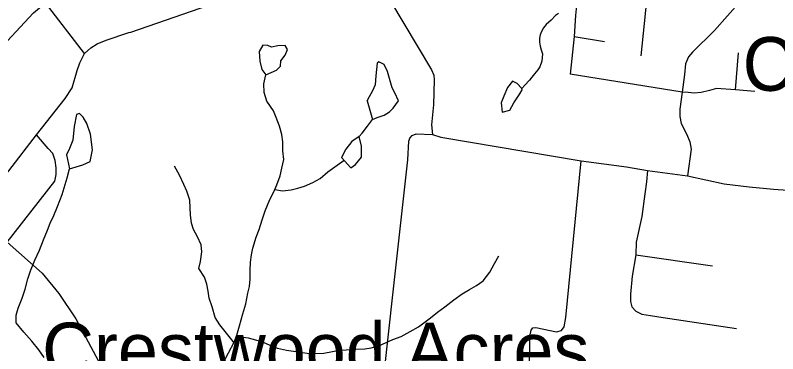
# Model space of a CAD drawing. Extents: x 0 to 34, y 0 to 22.
# Drawn here: x 2.395 to 3.515, y 16.285 to 16.783 of the extents above; entities that cross this region are included whole.
import ezdxf

# ---------------------------------------------------------------- set-up
doc = ezdxf.new("R2010")
doc.units = 0
for name, color, linetype in [('GM_X_County_Road', 7, 'Continuous'), ('GM_X_Interstate_Route', 7, 'Continuous'), ('GM_X_Minor_Lake', 7, 'Continuous'), ('GM_X_Minor_River', 7, 'Continuous'), ('GM_X_Township_Subdivision', 7, 'Continuous'), ('GM_X_Unincorporated_Text', 7, 'Continuous')]:
    doc.layers.add(name, color=color, linetype=linetype)

msp = doc.modelspace()

# ---------------------------------------------------------------- linework, layer by layer
at = {"layer": 'GM_X_County_Road'}
for points in [[(2.5645, 16.7579), (2.6921, 16.8018), (2.7129, 16.8072), (2.7415, 16.8122), (2.8434, 16.8208), (2.8888, 16.8307), (2.925, 16.8393)], [(2.925, 16.8393), (3.0063, 16.7023), (3.0099, 16.6947), (3.0101, 16.6874), (3.0094, 16.6508), (3.0062, 16.6215), (3.0077, 16.6072)], [(2.4966, 16.7263), (2.4393, 16.8007), (2.4357, 16.8056)], [(2.3395, 16.5036), (2.3546, 16.5175), (2.3853, 16.5537), (2.4262, 16.6065), (2.4679, 16.6603), (2.4783, 16.676), (2.4859, 16.7014), (2.4895, 16.7128), (2.4966, 16.7263), (2.5057, 16.7348), (2.5149, 16.7406), (2.5283, 16.7461), (2.5618, 16.757), (2.5645, 16.7579)], [(2.3831, 16.4487), (2.4531, 16.5388), (2.4547, 16.5483), (2.4548, 16.5581), (2.4534, 16.5688), (2.4501, 16.5791), (2.4433, 16.5867), (2.4262, 16.6065)], [(2.8559, 15.3242), (2.8828, 15.5776), (2.8823, 15.5871), (2.88, 15.6009), (2.8808, 15.6183), (2.8941, 15.7652), (2.913, 15.9963), (2.9286, 16.1743), (2.9306, 16.1979), (2.9499, 16.3756), (2.9714, 16.57), (2.9729, 16.5972), (2.9738, 16.6003), (2.9747, 16.6018), (2.978, 16.6059), (2.9836, 16.6083), (3.0077, 16.6072)], [(3.0077, 16.6072), (3.0199, 16.6034), (3.2263, 16.5685), (3.2928, 16.5595), (3.3237, 16.5541), (3.3826, 16.5464), (3.4363, 16.5348), (3.4732, 16.5304), (3.5089, 16.527), (3.5443, 16.5245), (3.6987, 16.5072), (3.6996, 16.5071)], [(3.2878, 15.9702), (3.2906, 16.01), (3.287, 16.0204), (3.2811, 16.0285), (3.1838, 16.1424), (3.1651, 16.1641), (3.1565, 16.1802), (3.1523, 16.1945), (3.1498, 16.2167), (3.1509, 16.3102), (3.153, 16.3194), (3.1554, 16.3229), (3.1594, 16.3234), (3.1901, 16.3171), (3.1974, 16.3189), (3.2011, 16.3245), (3.2039, 16.3381), (3.2263, 16.5685)], [(2.2074, 16.5345), (2.2273, 16.5312), (2.2755, 16.511), (2.3238, 16.4892), (2.3831, 16.4487), (2.4345, 16.4035), (2.4589, 16.3735), (2.484, 16.336), (2.5458, 16.2199), (2.6419, 16.0249), (2.6836, 15.948), (2.7291, 15.8843), (2.758, 15.8531), (2.7648, 15.8462)]]:
    msp.add_lwpolyline(points, dxfattribs=at)
at = {"layer": 'GM_X_Interstate_Route'}
msp.add_lwpolyline([(2.181, 16.4629), (2.2273, 16.5312), (2.2674, 16.589), (2.34, 16.6943), (2.3633, 16.7237), (2.4215, 16.7861), (2.4393, 16.8007), (2.4586, 16.8179), (2.4894, 16.8393), (2.7155, 16.9908), (2.8497, 17.0804), (2.9292, 17.1425), (3.0025, 17.2108), (3.0522, 17.2646), (3.1203, 17.3605), (3.2374, 17.5377), (3.2788, 17.5999), (3.3097, 17.642), (3.3406, 17.6772), (3.3886, 17.7251), (3.5019, 17.8134), (3.5855, 17.8769), (3.6539, 17.9292), (3.721, 17.9807)], dxfattribs=at)
at = {"layer": 'GM_X_Minor_Lake'}
for points in [[(2.7627, 16.6952), (2.7784, 16.7018), (2.7843, 16.7077), (2.7852, 16.7157), (2.7911, 16.7239), (2.7947, 16.7322), (2.7914, 16.7383), (2.7808, 16.7378), (2.7712, 16.7358), (2.7659, 16.7382), (2.7587, 16.7387), (2.7532, 16.7293), (2.754, 16.7152)], [(2.754, 16.7152), (2.7572, 16.7026), (2.7627, 16.6952)], [(2.9196, 16.6293), (2.9265, 16.6324), (2.9368, 16.6356), (2.9446, 16.6407), (2.95, 16.6459), (2.9578, 16.6568), (2.9524, 16.6683), (2.9484, 16.676), (2.9445, 16.6897), (2.9417, 16.7001), (2.937, 16.7104), (2.9291, 16.714), (2.9264, 16.7122), (2.9245, 16.6936), (2.9238, 16.6803), (2.9198, 16.6713), (2.9147, 16.6627), (2.9115, 16.6563)], [(2.9196, 16.6293), (2.9265, 16.6324), (2.9368, 16.6356), (2.9446, 16.6407), (2.95, 16.6459), (2.9578, 16.6568), (2.9524, 16.6683), (2.9484, 16.676), (2.9445, 16.6897), (2.9417, 16.7001), (2.937, 16.7104), (2.9291, 16.714), (2.9264, 16.7122), (2.9245, 16.6936), (2.9238, 16.6803), (2.9198, 16.6713), (2.9147, 16.6627), (2.9116, 16.6566)], [(3.139, 16.6747), (3.132, 16.6822), (3.1252, 16.6857), (3.1178, 16.6764)], [(3.1178, 16.6764), (3.1126, 16.6636), (3.1085, 16.6538), (3.1101, 16.6401), (3.1212, 16.6429), (3.1275, 16.6538), (3.1362, 16.6669), (3.1393, 16.6729), (3.139, 16.6747)], [(2.9116, 16.6566), (2.9196, 16.6293)], [(2.4743, 16.5569), (2.4939, 16.5626), (2.505, 16.5673), (2.5084, 16.5847), (2.5055, 16.6076), (2.4998, 16.6233), (2.4947, 16.6329), (2.4891, 16.6383), (2.4849, 16.6365), (2.4811, 16.6188), (2.4795, 16.5987), (2.4747, 16.5866), (2.4703, 16.5772)], [(2.8893, 16.5971), (2.8807, 16.5856), (2.8739, 16.5736), (2.888, 16.5584), (2.8946, 16.5632), (2.9036, 16.574), (2.9035, 16.59), (2.9001, 16.6045)], [(2.9001, 16.6045), (2.8893, 16.5971)], [(2.4703, 16.5772), (2.4743, 16.5569)]]:
    msp.add_lwpolyline(points, dxfattribs=at)
at = {"layer": 'GM_X_Minor_River'}
for points in [[(3.193, 16.7854), (3.1883, 16.7821), (3.182, 16.7754), (3.175, 16.7691), (3.1711, 16.7643), (3.1679, 16.7587), (3.1659, 16.7538), (3.165, 16.7488), (3.1652, 16.7431), (3.1662, 16.737), (3.1675, 16.7316), (3.1693, 16.7259), (3.1686, 16.7152), (3.1654, 16.7069), (3.1626, 16.7021), (3.1578, 16.6965), (3.1539, 16.6916), (3.1504, 16.6872), (3.1433, 16.6798), (3.139, 16.6747)], [(2.7023, 16.2748), (2.7083, 16.2861), (2.7163, 16.3019), (2.7203, 16.3121), (2.7244, 16.3257), (2.7291, 16.3434), (2.7336, 16.3581), (2.7366, 16.3737), (2.7388, 16.3835), (2.7398, 16.3945), (2.7397, 16.4071), (2.7404, 16.4196), (2.7418, 16.4302), (2.744, 16.44), (2.7485, 16.4563), (2.753, 16.4676), (2.7575, 16.4819), (2.762, 16.4951), (2.7689, 16.5117), (2.7749, 16.523), (2.7789, 16.5331), (2.7838, 16.5463), (2.7863, 16.5577), (2.7893, 16.5705), (2.7881, 16.5831), (2.7877, 16.5964), (2.7864, 16.6071), (2.7829, 16.6197), (2.7783, 16.6324), (2.7743, 16.642), (2.7644, 16.656), (2.7606, 16.669), (2.7601, 16.6815), (2.7627, 16.6952)], [(2.9001, 16.6045), (2.9043, 16.6092), (2.9121, 16.6193), (2.9196, 16.6293)], [(2.7763, 16.5265), (2.7874, 16.5242), (2.8, 16.5258), (2.8099, 16.5282), (2.8195, 16.531), (2.8322, 16.5368), (2.8426, 16.5426), (2.8538, 16.5522), (2.8778, 16.5695)], [(2.7159, 16.3011), (2.7151, 16.3027), (2.6952, 16.3271), (2.6883, 16.3379), (2.6841, 16.3536), (2.6798, 16.3667), (2.6782, 16.3766), (2.6762, 16.3873), (2.6726, 16.3973), (2.6646, 16.41), (2.6667, 16.4206), (2.669, 16.4346), (2.6681, 16.4449), (2.6627, 16.4565), (2.6568, 16.4673), (2.6537, 16.4769), (2.652, 16.4891), (2.6519, 16.4993), (2.6511, 16.5108), (2.6468, 16.5238), (2.6425, 16.5338), (2.636, 16.5473), (2.6287, 16.5604)], [(2.4372, 16.2794), (2.4295, 16.2903), (2.4191, 16.3031), (2.4073, 16.3163), (2.3962, 16.3302), (2.3961, 16.3413), (2.399, 16.3519), (2.4047, 16.3665), (2.4092, 16.3798), (2.4134, 16.3949), (2.4171, 16.4066), (2.4236, 16.4224), (2.4304, 16.437), (2.4361, 16.4525), (2.4421, 16.4664), (2.4462, 16.4766), (2.4514, 16.4883), (2.4566, 16.5014), (2.4635, 16.5191), (2.4681, 16.5335), (2.471, 16.5433), (2.4743, 16.5569)], [(2.7198, 16.3108), (2.7263, 16.3096), (2.7369, 16.3082), (2.7479, 16.3053), (2.7588, 16.3016), (2.7686, 16.2976), (2.7799, 16.2931), (2.7931, 16.2901), (2.8034, 16.2887), (2.8132, 16.287), (2.8238, 16.2856), (2.8348, 16.2849), (2.8481, 16.2854), (2.8607, 16.2881), (2.8706, 16.2901), (2.8809, 16.2903), (2.895, 16.2914), (2.9083, 16.2919), (2.9178, 16.2932), (2.9289, 16.2963), (2.9397, 16.3014), (2.9497, 16.3057), (2.962, 16.3103), (2.975, 16.3173), (2.987, 16.3242), (3.0048, 16.3378), (3.0149, 16.3459), (3.0257, 16.3537), (3.0393, 16.364), (3.0513, 16.3728), (3.0624, 16.3794), (3.0725, 16.3849), (3.0821, 16.3922), (3.0919, 16.4045), (3.0991, 16.4177), (3.1051, 16.4289)]]:
    msp.add_lwpolyline(points, dxfattribs=at)
at = {"layer": 'GM_X_Township_Subdivision'}
for points in [[(3.2267, 16.9013), (3.2264, 16.898), (3.2266, 16.87), (3.2207, 16.8119), (3.2179, 16.7821), (3.2161, 16.7511), (3.2099, 16.6961)], [(3.8766, 16.8608), (3.8386, 16.8639), (3.6602, 16.8815), (3.5812, 16.8884), (3.5665, 16.887), (3.553, 16.8832), (3.541, 16.877), (3.5216, 16.8628), (3.4605, 16.8035), (3.4221, 16.7604), (3.3897, 16.7285), (3.3838, 16.7214), (3.3793, 16.711), (3.3779, 16.6956), (3.3748, 16.6696), (3.3712, 16.6447), (3.371, 16.6339), (3.3731, 16.6233), (3.3815, 16.607), (3.3861, 16.5965), (3.388, 16.5857), (3.3826, 16.5464)], [(3.3142, 16.7228), (3.3227, 16.804), (3.3281, 16.8554)], [(3.2161, 16.7511), (3.2604, 16.7439)], [(3.453, 16.6729), (3.4573, 16.7272)], [(3.4816, 16.6706), (3.453, 16.6729), (3.4251, 16.6747), (3.4147, 16.6718), (3.4027, 16.669), (3.3922, 16.6681), (3.3833, 16.6689), (3.3748, 16.6696), (3.2099, 16.6961)], [(3.3237, 16.5541), (3.3221, 16.5374), (3.3199, 16.5197), (3.3155, 16.4865), (3.307, 16.449), (3.3067, 16.43), (3.301, 16.399), (3.2988, 16.3725), (3.2988, 16.3618), (3.3007, 16.3539), (3.3063, 16.3472), (3.3152, 16.3431), (3.3281, 16.3409), (3.3465, 16.3381), (3.4545, 16.322)], [(3.3067, 16.43), (3.4194, 16.4142)]]:
    msp.add_lwpolyline(points, dxfattribs=at)

# ---------------------------------------------------------------- texts
at = {"layer": 'GM_X_Unincorporated_Text'}
for s, p in [('Colerain Heights', (3.4634, 16.6715)), ('Crestwood Acres', (2.4342, 16.2515))]:
    msp.add_text(s, height=0.078977, rotation=0, dxfattribs=at).set_placement(p)

doc.saveas('drawing.dxf')
